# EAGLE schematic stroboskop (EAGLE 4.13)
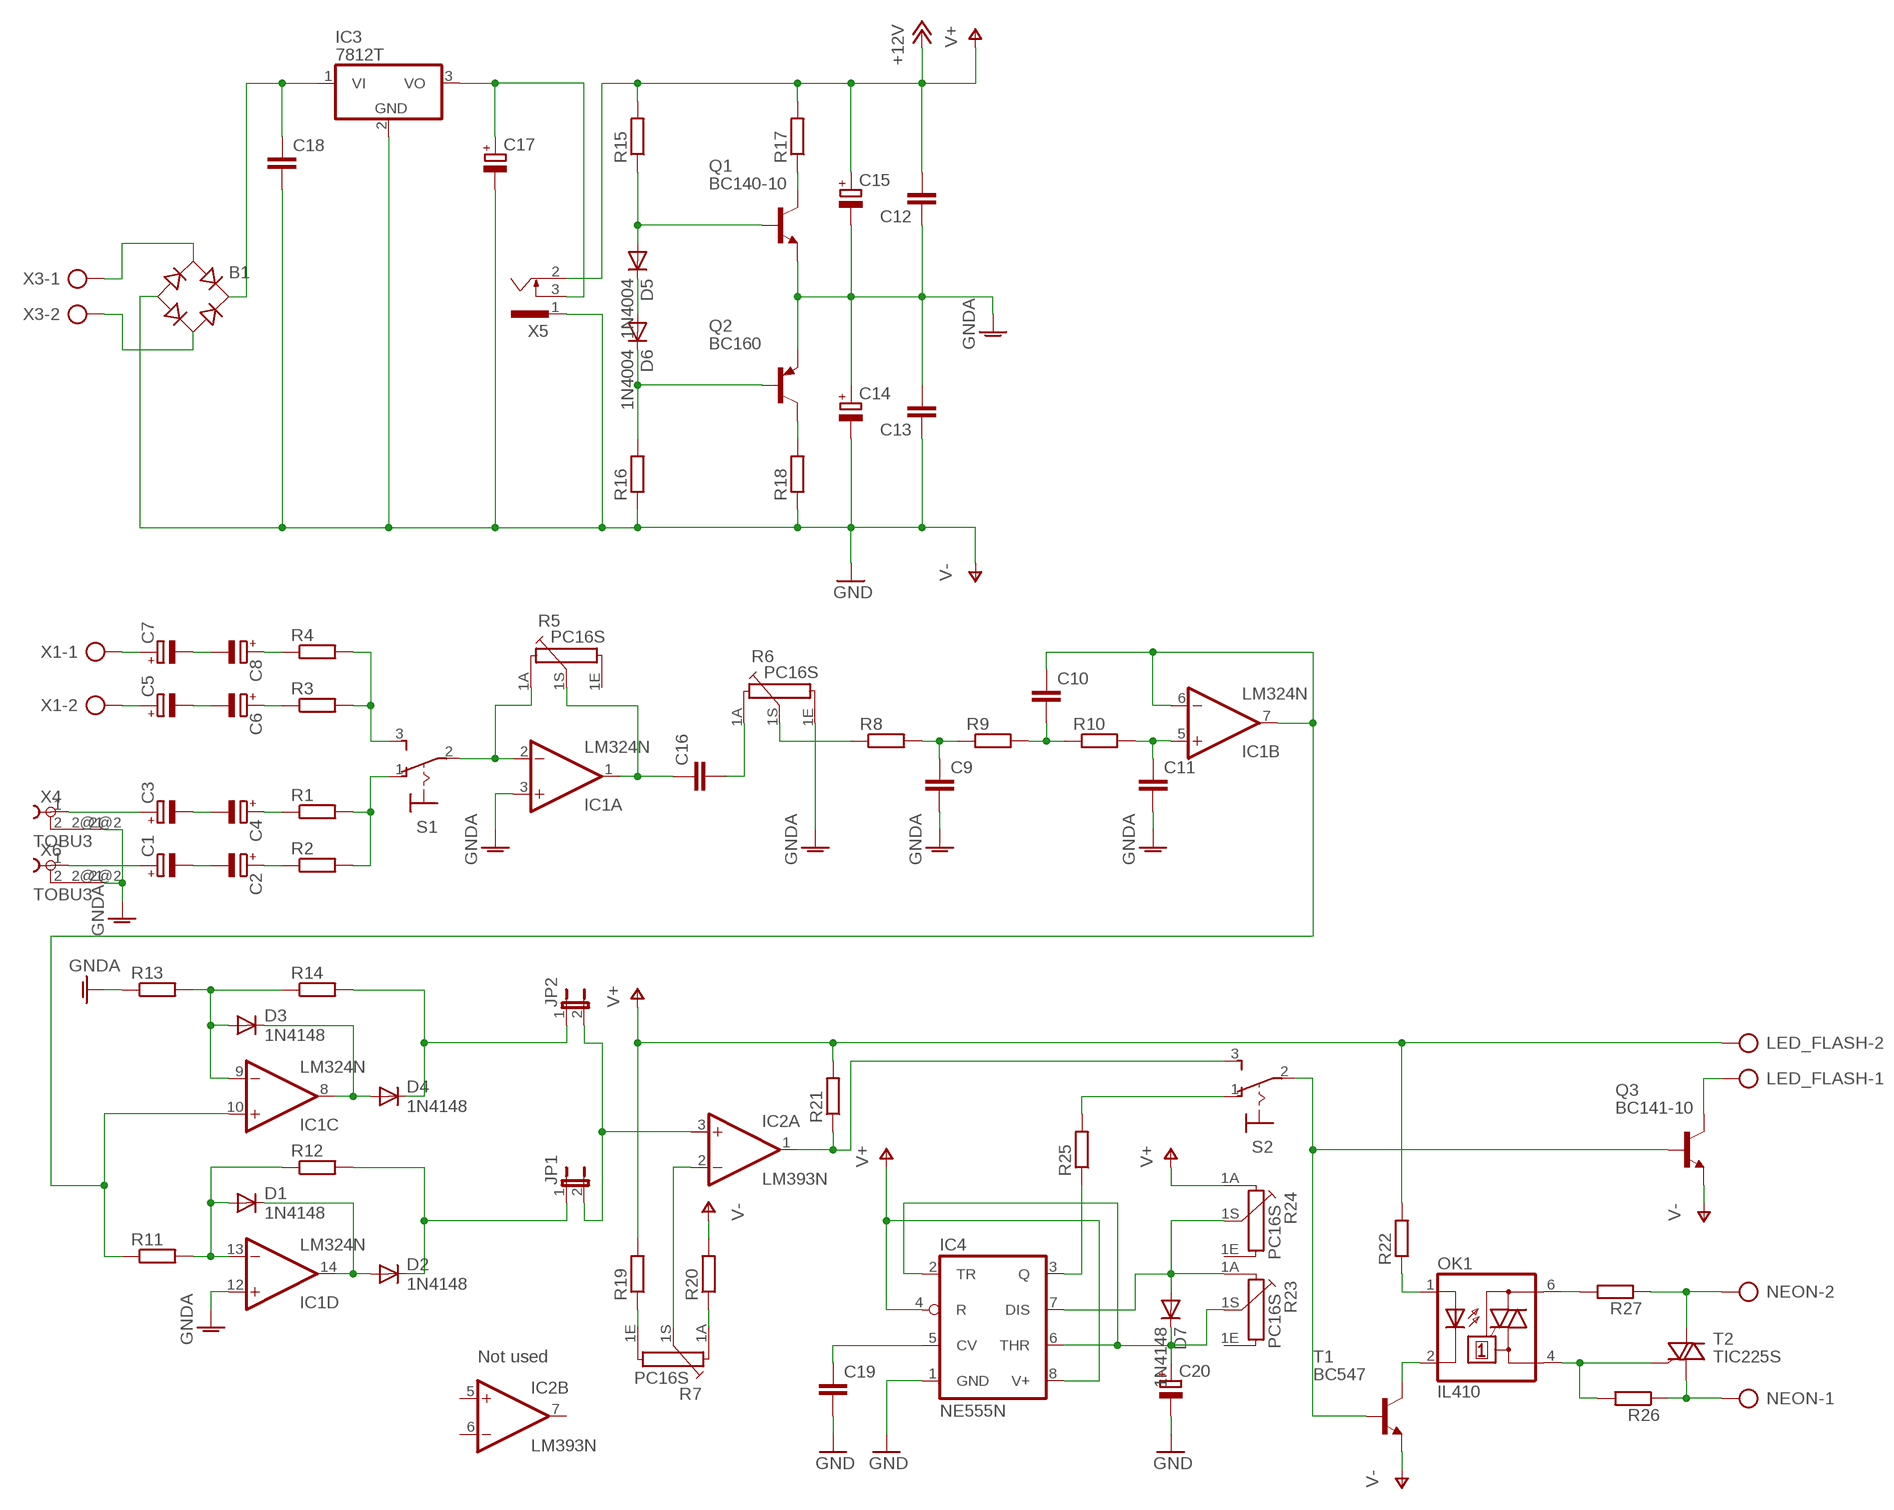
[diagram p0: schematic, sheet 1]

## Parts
B1  RB1A  [RB1A]
C1  CPOL-EUE5-10.5  [E5-10,5]
C2  CPOL-EUE5-10.5  [E5-10,5]
C3  CPOL-EUE5-10.5  [E5-10,5]
C4  CPOL-EUE5-10.5  [E5-10,5]
C5  CPOL-EUE2.5-5  [E2,5-5]
C6  CPOL-EUE2.5-5  [E2,5-5]
C7  CPOL-EUE2.5-5  [E2,5-5]
C8  CPOL-EUE2.5-5  [E2,5-5]
C9  C-EU050-024X044  [C050-024X044]
C10  C-EU050-025X075  [C050-025X075]
C11  C-EU025-025X050  [C025-025X050]
C12  C-EU050-025X075  [C050-025X075]
C13  C-EU050-025X075  [C050-025X075]
C14  CPOL-EUE5-10.5  [E5-10,5]
C15  CPOL-EUE5-10.5  [E5-10,5]
C16  C-EU050-024X044  [C050-024X044]
C17  CPOL-EUE5-10.5  [E5-10,5]
C18  C-EU050-025X075  [C050-025X075]
C19  C-EU050-025X075  [C050-025X075]
C20  CPOL-EUE2,5-6E  [E2,5-6E]
D1  1N4148  [DO35-10]
D2  1N4148  [DO35-10]
D3  1N4148  [DO35-10]
D4  1N4148  [DO35-10]
D5  1N4004  [DO41-10]
D6  1N4004  [DO41-10]
D7  1N4148  [DO35-10]
IC1  LM324N  [DIL14]
IC2  LM393N  [DIL08]
IC3  7812T  [TO220H]
IC4  NE555N  [DIL08]
JP1  JP1E  [JP1]
JP2  JP1E  [JP1]
LED_FLASH  AK300/2  [AK300/2]
NEON  AK300/2  [AK300/2]
OK1  IL410  [DIL06]
Q1  BC140-10  [TO39]
Q2  BC160  [TO39]
Q3  BC141-10  [TO39]
R1  R-EU_0207/10  [0207/10]
R2  R-EU_0207/10  [0207/10]
R3  R-EU_0207/10  [0207/10]
R4  R-EU_0207/10  [0207/10]
R5  PC16S  [PC16S]
R6  PC16S  [PC16S]
R7  PC16S  [PC16S]
R8  R-EU_0207/10  [0207/10]
R9  R-EU_0207/10  [0207/10]
R10  R-EU_0207/10  [0207/10]
R11  R-EU_0207/10  [0207/10]
R12  R-EU_0207/10  [0207/10]
R13  R-EU_0207/10  [0207/10]
R14  R-EU_0207/10  [0207/10]
R15  R-EU_0207/10  [0207/10]
R16  R-EU_0207/10  [0207/10]
R17  R-EU_0207/10  [0207/10]
R18  R-EU_0207/10  [0207/10]
R19  R-EU_0207/10  [0207/10]
R20  R-EU_0207/10  [0207/10]
R21  R-EU_0207/10  [0207/10]
R22  R-EU_0207/10  [0207/10]
R23  PC16S  [PC16S]
R24  PC16S  [PC16S]
R25  R-EU_0207/10  [0207/10]
R26  R-EU_0207/10  [0207/10]
R27  R-EU_0207/10  [0207/10]
S1  320-916  [320-916]
S2  320-916  [320-916]
T1  BC547  [TO92]
T2  TIC225S  [TO220DS]
X1  AK300/2  [AK300/2]
X3  AK300/2  [AK300/2]
X4  TOBU3  [TOBU3]
X5  733989-55  [733989-5]
X6  TOBU3  [TOBU3]

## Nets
GND: C19.2 C20.- IC4.1(GND)
GNDA: C9.2 C11.2 C12.1 C13.2 C14.+ C15.- IC1.3(A:+IN) IC1.12(D:+IN) Q1.1(E) Q2.1(E) R6.1E R13.1 X4.2@2 X6.2@2
N$1: C7.- C8.-
N$2: C5.- C6.-
N$3: C3.- C4.-
N$4: C1.- C2.-
N$5: C4.+ R1.1
N$6: C2.+ R2.1
N$7: C8.+ R4.1
N$8: C6.+ R3.1
N$9: R3.2 R4.2 S1.3(S)
N$10: R1.2 R2.2 S1.1(O)
N$11: IC1.2(A:-IN) R5.1A S1.2(P)
N$12: C16.1 IC1.1(A:OUT) R5.1S
N$13: R6.1S R8.1
N$14: C9.1 R8.2 R9.1
N$15: C10.2 R9.2 R10.1
N$16: C11.1 IC1.5(B:+IN) R10.2
N$17: C10.1 IC1.6(B:-IN) IC1.7(B:OUT) IC1.10(C:+IN) R11.1
N$18: D1.A IC1.13(D:-IN) R11.2 R12.1
N$19: D1.C D2.A IC1.14(D:OUT)
N$20: D2.C JP1.1 R12.2
N$21: C16.2 R6.1A
N$22: D3.A IC1.9(C:-IN) R13.2 R14.1
N$23: D3.C D4.A IC1.8(C:OUT)
N$24: D4.C JP2.1 R14.2
N$25: IC2.3(A:+IN) JP1.2 JP2.2
N$26: IC2.2(A:-IN) R7.1S
N$27: C7.+ X1.1
N$28: C5.+ X1.2
N$29: C3.+ X4.1
N$30: C1.+ X6.1
N$31: IC2.1(A:OUT) R21.1 S2.3(S)
N$32: R7.1E R19.1
N$33: Q1.3(C) R17.1
N$34: Q2.3(C) R18.2
N$35: D5.A Q1.2(B) R15.1
N$36: D5.C D6.A
N$37: D6.C Q2.2(B) R16.2
N$38: R7.1A R20.1
N$39: LED_FLASH.1 Q3.3(C)
N$40: OK1.1(A) R22.1
N$41: OK1.2(C) T1.3(C)
N$42: B1.AC1 X3.1
N$43: B1.AC2 X3.2
N$44: B1.+ C18.1 IC3.1(VI)
N$45: R25.2 S2.1(O)
N$46: C17.+ IC3.3(VO) X5.3
N$47: C19.1 IC4.5(CV)
N$48: C20.+ D7.C IC4.2(TR) IC4.6(THR) R23.1S
N$49: OK1.4(A1) R26.2 T2.G
N$50: D7.A IC4.7(DIS) R23.1A R24.1S
N$51: NEON.1 R26.1 T2.A1
N$52: IC4.3(Q) R25.1
N$53: Q3.2(B) S2.2(P) T1.2(B)
N$54: OK1.6(A2) R27.2
N$55: NEON.2 R27.1 T2.A2
V+: C12.2 C15.+ IC4.4(R) IC4.8(V+) LED_FLASH.2 R15.2 R17.2 R19.2 R21.2 R22.2 R24.1A X5.2 ; supply symbol labelled +12V
V-: B1.- C13.1 C14.- C17.- C18.2 IC3.2(GND) Q3.1(E) R16.1 R18.1 R20.2 T1.1(E) X5.1 ; supply symbol labelled GND
Unconnected: IC2.5(B:+IN) IC2.6(B:-IN) IC2.7(B:OUT) R5.1E R23.1E R24.1E X4.2 X4.2@1 X6.2 X6.2@1

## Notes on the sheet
- Not used

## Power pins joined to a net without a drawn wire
V+: IC1.4(P:V+) IC2.8(P:V+)
V-: IC1.11(P:V-) IC2.4(P:V-)

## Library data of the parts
B1 = rectifier:RB1A: RECTIFIER 1 A
C1-C8 C14 C15 C17 C20 = rcl:CPOL-EU: POLARIZED CAPACITOR, European symbol
C9-C13 C16 C18 C19 = rcl:C-EU: CAPACITOR, European symbol
D1-D4 D7 = diode:1N4148: DIODE
D5 D6 = diode:1N4004: DIODE
IC1 = linear:LM324: OP AMP
IC2 = linear:LM393: COMPARATOR
IC3 = linear:78*: Positive VOLTAGE REGULATOR
IC4 = linear:*555: TIMER
JP1 JP2 = jumper:JP1E: JUMPER
LED_FLASH NEON X1 X3 = con-ptr500:AK300/2: CONNECTOR
OK1 = optocoupler:IL410: SIEMENS OPTO COUPLER
Q1 = transistor-npn:BC140-10: NPN Transistor
Q2 = transistor-pnp:BC160*: PNP Transistror
Q3 = transistor-npn:BC141-10: NPN Transistor
R1-R4 R8-R22 R25-R27 = rcl:R-EU_: RESISTOR, European symbol
R5-R7 R23 R24 = piher:PC16S: POTENTIOMETER single carbon potentiometer, 16 mm, S3ROH
S1 S2 = switch:320-916: TOGGLE SWITCH distributor RS Components
T1 = transistor:BC547: NPN TRANSISTOR
T2 = triac:TIC225S: TRIAC
X4 X6 = con-hirschmann:TOBU3: Female Cinch CONNECTOR
X5 = con-conrad:733989-55: FEMALE PRINT CONNECTOR Außen-Ø 4,2 mm, Innen 1.1 mm FUK HING Industries, distributor Conrad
